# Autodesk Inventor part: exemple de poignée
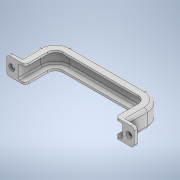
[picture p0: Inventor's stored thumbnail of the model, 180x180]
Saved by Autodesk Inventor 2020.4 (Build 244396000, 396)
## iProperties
Created: 2021-10
Part Number: exemple de poignée
Material: Générique
Document SubType Name: Modeling
Designer: mel
Density: 1 g/cm^3
Appearance: Par défaut
Author: mel
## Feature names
1. Balayage1
2. Extrusion1
3. Symétrie1 [Mirror]
4. Congé1 [Fillet]
## Parameters: d0 = 15 mm, d1 = 15 mm, d2 = 15 mm, d3 = 5 mm, d4 = 11.53846 mm, d5 = 11.53846 mm, d6 = 11.53846 mm, d7 = 2.5 mm, d10 = 12.5 mm, d11 = 12.5 mm, d12 = 0, d13 = 0, d14 = 5 mm, d17 = 7.5 mm, d18 = 16 mm, d19 = 5 mm, d20 = 0, d21 = 75 mm, d22 = 5 mm
